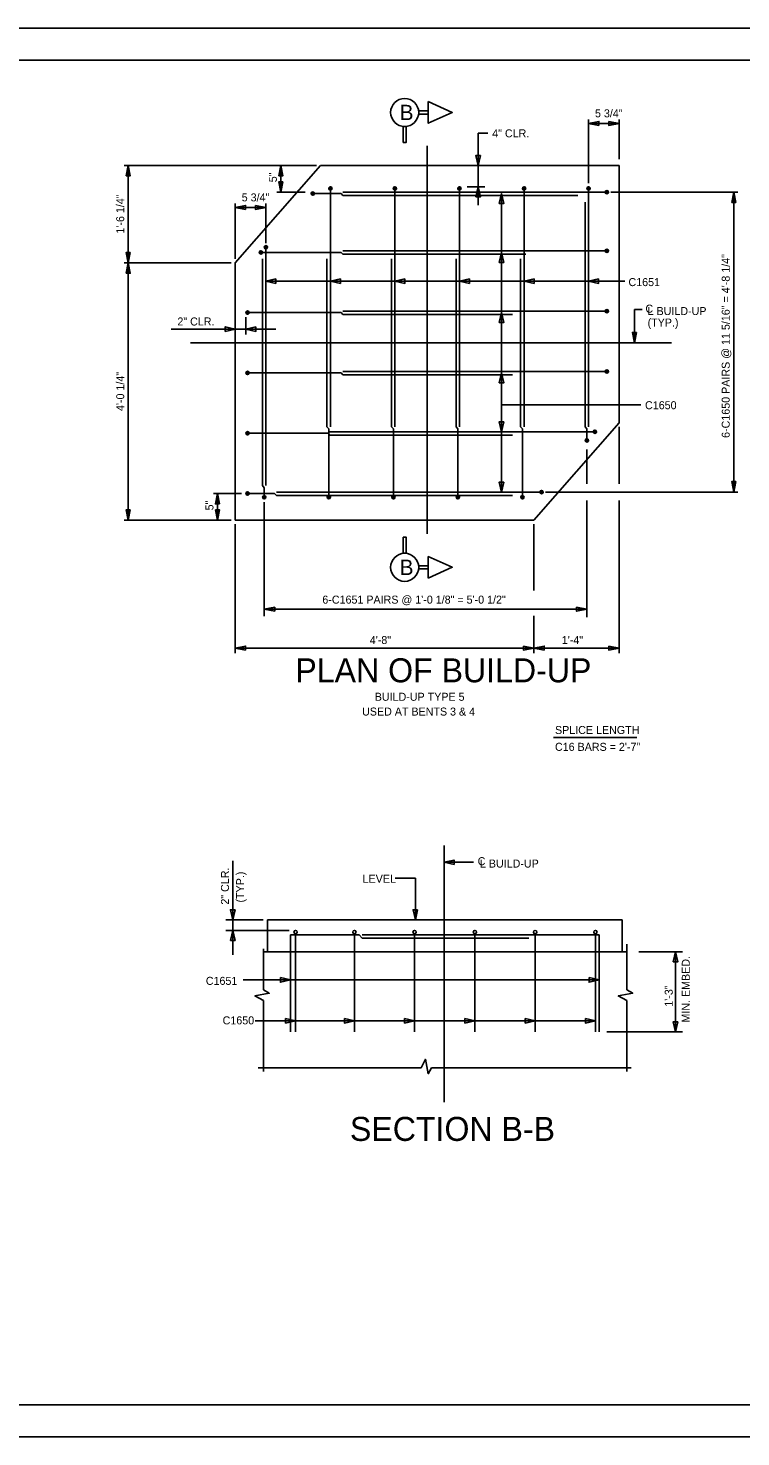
# Model space of a CAD drawing. Extents: x -133.1 to -97, y -110.1 to -88.1.
# Drawn here: x -121.69 to -110.56, y -110.1 to -88.1 of the extents above; entities that cross this region are included whole.
import ezdxf

# ---------------------------------------------------------------- set-up
doc = ezdxf.new("R2010")
doc.units = 0
for name, color, linetype in [('BR_AUTO DIMENSION', 7, 'Continuous'), ('BR_BORDER LINES', 7, 'Continuous'), ('BR_CENTER LINES', 7, 'Continuous'), ('BR_CONCRETE', 7, 'Continuous'), ('BR_REBAR', 7, 'Continuous'), ('BR_TEXT', 7, 'Continuous'), ('Default', 7, 'Continuous'), ('Level 31', 7, 'Continuous')]:
    doc.layers.add(name, color=color, linetype=linetype)

msp = doc.modelspace()

# ---------------------------------------------------------------- linework, layer by layer
at = {"layer": 'BR_AUTO DIMENSION'}
for p, q in [((-112.936, -90.525), (-112.936, -89.528)), ((-112.457, -90.148), (-112.457, -89.528)), ((-114.66, -90.866), (-114.66, -89.745)), ((-114.507, -89.745), (-114.66, -89.745)), ((-112.936, -89.59), (-112.457, -89.59)), ((-117.186, -90.245), (-120.191, -90.245)), ((-120.128, -91.766), (-120.128, -90.245)), ((-117.744, -90.245), (-117.744, -90.662)), ((-114.835, -90.579), (-114.554, -90.579)), ((-118.457, -91.704), (-118.457, -90.841)), ((-117.978, -91.461), (-117.978, -90.841)), ((-117.365, -90.662), (-117.806, -90.662)), ((-114.296, -90.685), (-114.296, -95.347)), ((-112.587, -90.662), (-110.605, -90.662)), ((-110.668, -95.347), (-110.668, -90.662)), ((-118.457, -90.903), (-117.978, -90.903)), ((-118.519, -91.766), (-120.191, -91.766)), ((-118.519, -91.766), (-120.191, -91.766)), ((-120.128, -95.787), (-120.128, -91.766)), ((-117.978, -92.053), (-112.371, -92.053)), ((-118.29, -92.617), (-118.29, -92.887)), ((-112.096, -92.498), (-112.219, -92.498)), ((-112.219, -92.498), (-112.219, -93.016)), ((-117.822, -92.803), (-119.456, -92.803)), ((-114.296, -93.983), (-112.117, -93.983)), ((-112.457, -94.329), (-112.457, -95.217)), ((-112.961, -94.682), (-112.961, -95.217)), ((-118.356, -95.37), (-118.797, -95.37)), ((-118.734, -95.787), (-118.734, -95.37)), ((-113.606, -95.347), (-110.605, -95.347)), ((-112.961, -95.477), (-112.961, -97.301)), ((-112.457, -95.477), (-112.457, -97.866)), ((-118.002, -95.504), (-118.002, -97.285)), ((-118.519, -95.787), (-120.191, -95.787)), ((-118.457, -95.85), (-118.457, -97.866)), ((-113.79, -95.85), (-113.79, -96.883)), ((-118.002, -97.178), (-112.961, -97.178)), ((-113.79, -97.279), (-113.79, -97.866)), ((-118.457, -97.784), (-113.79, -97.784)), ((-113.79, -97.784), (-112.457, -97.784)), ((-113.486, -99.183), (-112.181, -99.183)), ((-118.495, -101.109), (-118.495, -102.574)), ((-115.194, -101.13), (-114.735, -101.13)), ((-115.959, -101.376), (-115.642, -101.376)), ((-115.642, -101.376), (-115.642, -102.026)), ((-118.022, -102.026), (-118.604, -102.026)), ((-117.616, -102.193), (-118.604, -102.193)), ((-112.149, -102.527), (-111.47, -102.527)), ((-111.576, -102.527), (-111.576, -103.777)), ((-112.771, -102.966), (-118.331, -102.966)), ((-112.828, -103.606), (-118.147, -103.606)), ((-116.595, -103.606), (-116.675, -103.606)), ((-116.348, -103.606), (-116.428, -103.606)), ((-115.653, -103.606), (-115.733, -103.606)), ((-114.712, -103.606), (-114.792, -103.606)), ((-113.77, -103.606), (-113.85, -103.606)), ((-112.828, -103.606), (-112.908, -103.606)), ((-112.65, -103.777), (-111.47, -103.777))]:
    msp.add_line(p, q, dxfattribs=at)
for points in [[(-112.774, -89.621), (-112.936, -89.59), (-112.774, -89.559)], [(-112.619, -89.559), (-112.457, -89.59), (-112.619, -89.621)], [(-114.624, -90.089), (-114.66, -90.245), (-114.696, -90.089)], [(-120.16, -90.408), (-120.128, -90.245), (-120.097, -90.408)], [(-117.775, -90.408), (-117.744, -90.245), (-117.712, -90.408)], [(-117.712, -90.5), (-117.744, -90.662), (-117.775, -90.5)], [(-114.696, -90.735), (-114.66, -90.579), (-114.624, -90.735)], [(-114.332, -90.841), (-114.296, -90.685), (-114.26, -90.841)], [(-110.699, -90.825), (-110.668, -90.662), (-110.637, -90.825)], [(-118.294, -90.934), (-118.457, -90.903), (-118.294, -90.872)], [(-118.14, -90.872), (-117.978, -90.903), (-118.14, -90.934)], [(-120.097, -91.604), (-120.128, -91.766), (-120.16, -91.604)], [(-114.332, -91.76), (-114.296, -91.604), (-114.26, -91.76)], [(-120.16, -91.929), (-120.128, -91.766), (-120.097, -91.929)], [(-117.822, -92.017), (-117.978, -92.053), (-117.822, -92.089)], [(-116.813, -92.017), (-116.969, -92.053), (-116.813, -92.089)], [(-115.805, -92.017), (-115.961, -92.053), (-115.805, -92.089)], [(-114.797, -92.017), (-114.953, -92.053), (-114.797, -92.089)], [(-113.788, -92.017), (-113.944, -92.053), (-113.788, -92.089)], [(-112.78, -92.017), (-112.936, -92.053), (-112.78, -92.089)], [(-114.332, -92.701), (-114.296, -92.545), (-114.26, -92.701)], [(-118.613, -92.839), (-118.457, -92.803), (-118.613, -92.767)], [(-118.134, -92.767), (-118.29, -92.803), (-118.134, -92.839)], [(-112.188, -92.854), (-112.219, -93.016), (-112.251, -92.854)], [(-114.332, -93.643), (-114.296, -93.487), (-114.26, -93.643)], [(-114.26, -94.25), (-114.296, -94.406), (-114.332, -94.25)], [(-114.26, -95.191), (-114.296, -95.347), (-114.332, -95.191)], [(-110.637, -95.185), (-110.668, -95.347), (-110.699, -95.185)], [(-118.703, -95.533), (-118.734, -95.37), (-118.765, -95.533)], [(-120.097, -95.625), (-120.128, -95.787), (-120.16, -95.625)], [(-118.765, -95.625), (-118.734, -95.787), (-118.703, -95.625)], [(-117.84, -97.209), (-118.002, -97.178), (-117.84, -97.147)], [(-113.123, -97.147), (-112.961, -97.178), (-113.123, -97.209)], [(-118.294, -97.815), (-118.457, -97.784), (-118.294, -97.752)], [(-113.953, -97.752), (-113.79, -97.784), (-113.953, -97.815)], [(-113.628, -97.815), (-113.79, -97.784), (-113.628, -97.752)], [(-112.619, -97.752), (-112.457, -97.784), (-112.619, -97.815)], [(-115.038, -101.166), (-115.194, -101.13), (-115.038, -101.094)], [(-118.459, -101.87), (-118.495, -102.026), (-118.531, -101.87)], [(-115.606, -101.87), (-115.642, -102.026), (-115.678, -101.87)], [(-118.531, -102.349), (-118.495, -102.193), (-118.459, -102.349)], [(-111.612, -102.683), (-111.576, -102.527), (-111.54, -102.683)], [(-117.75, -102.93), (-117.594, -102.966), (-117.75, -103.002)], [(-112.927, -102.93), (-112.771, -102.966), (-112.927, -103.002)], [(-117.669, -103.57), (-117.513, -103.606), (-117.669, -103.642)], [(-116.751, -103.57), (-116.595, -103.606), (-116.751, -103.642)], [(-115.809, -103.57), (-115.653, -103.606), (-115.809, -103.642)], [(-114.868, -103.57), (-114.712, -103.606), (-114.868, -103.642)], [(-113.926, -103.57), (-113.77, -103.606), (-113.926, -103.642)], [(-112.984, -103.57), (-112.828, -103.606), (-112.984, -103.642)], [(-111.54, -103.621), (-111.576, -103.777), (-111.612, -103.621)]]:
    msp.add_lwpolyline(points, close=True, dxfattribs=at)
at = {"layer": 'BR_BORDER LINES'}
for p, q in [((-97.642, -88.603), (-131.308, -88.603)), ((-131.308, -109.603), (-97.642, -109.603))]:
    msp.add_line(p, q, dxfattribs=at)
at = {"layer": 'BR_CENTER LINES'}
for p, q in [((-115.457, -89.942), (-115.457, -95.998)), ((-119.154, -93.016), (-111.642, -93.016)), ((-115.194, -100.868), (-115.194, -104.877))]:
    msp.add_line(p, q, dxfattribs=at)
at = {"layer": 'BR_CONCRETE'}
for p, q in [((-118.457, -91.766), (-117.124, -90.245)), ((-112.457, -90.245), (-117.124, -90.245)), ((-112.457, -94.266), (-112.457, -90.245)), ((-118.457, -91.766), (-118.457, -95.787)), ((-113.79, -95.787), (-112.457, -94.266)), ((-113.79, -95.787), (-118.457, -95.787)), ((-117.953, -102.026), (-117.953, -102.527)), ((-117.953, -102.026), (-112.412, -102.026)), ((-112.412, -102.026), (-112.412, -102.527)), ((-118.015, -102.527), (-112.338, -102.527))]:
    msp.add_line(p, q, dxfattribs=at)
at = {"layer": 'BR_REBAR'}
for p, q in [((-116.969, -90.579), (-116.969, -94.329)), ((-115.961, -90.579), (-115.961, -94.329)), ((-114.953, -90.579), (-114.953, -94.329)), ((-113.944, -90.579), (-113.944, -94.329)), ((-112.936, -90.579), (-112.936, -94.329)), ((-117.271, -90.685), (-116.802, -90.685)), ((-116.802, -90.685), (-116.774, -90.716)), ((-116.774, -90.662), (-112.624, -90.662)), ((-116.774, -90.716), (-113.104, -90.716)), ((-112.99, -90.818), (-112.99, -94.329)), ((-117.978, -91.497), (-117.978, -95.247)), ((-118.081, -91.604), (-116.802, -91.604)), ((-118.032, -91.704), (-118.032, -95.247)), ((-117.023, -91.704), (-117.023, -94.329)), ((-116.802, -91.604), (-116.774, -91.634)), ((-116.774, -91.581), (-112.624, -91.581)), ((-116.774, -91.634), (-113.914, -91.634)), ((-116.015, -91.704), (-116.015, -94.329)), ((-115.005, -91.704), (-115.005, -94.329)), ((-113.998, -91.704), (-113.998, -94.329)), ((-118.29, -92.545), (-116.802, -92.545)), ((-116.802, -92.545), (-116.774, -92.576)), ((-116.774, -92.522), (-112.624, -92.522)), ((-116.774, -92.576), (-114.124, -92.576)), ((-118.29, -93.487), (-116.802, -93.487)), ((-116.802, -93.487), (-116.774, -93.517)), ((-116.774, -93.464), (-112.624, -93.464)), ((-116.774, -93.517), (-114.124, -93.517)), ((-117.023, -94.329), (-116.994, -94.36)), ((-116.994, -94.36), (-116.994, -95.454)), ((-116.015, -94.329), (-115.986, -94.36)), ((-115.986, -94.36), (-115.986, -95.454)), ((-115.005, -94.329), (-114.977, -94.359)), ((-114.977, -94.359), (-114.977, -95.454)), ((-113.998, -94.329), (-113.969, -94.36)), ((-113.969, -94.36), (-113.969, -95.454)), ((-112.99, -94.329), (-112.961, -94.36)), ((-112.961, -94.36), (-112.961, -94.568)), ((-118.29, -94.429), (-117.006, -94.429)), ((-117.006, -94.429), (-116.978, -94.459)), ((-116.978, -94.406), (-112.811, -94.406)), ((-116.978, -94.459), (-114.124, -94.459)), ((-118.032, -95.247), (-118.002, -95.279)), ((-118.29, -95.37), (-117.842, -95.37)), ((-118.002, -95.279), (-118.002, -95.454)), ((-117.842, -95.37), (-117.813, -95.401)), ((-117.813, -95.401), (-114.124, -95.401)), ((-117.809, -95.347), (-113.643, -95.347)), ((-117.594, -102.265), (-117.594, -103.777)), ((-116.521, -102.265), (-117.594, -102.265)), ((-117.513, -103.777), (-117.513, -102.245)), ((-116.595, -103.777), (-116.595, -102.245)), ((-116.521, -102.265), (-116.473, -102.317)), ((-112.771, -102.264), (-116.473, -102.264)), ((-115.653, -103.777), (-115.653, -102.245)), ((-114.712, -103.777), (-114.712, -102.245)), ((-113.77, -103.777), (-113.77, -102.245)), ((-112.828, -103.777), (-112.828, -102.245)), ((-112.771, -102.264), (-112.771, -103.777)), ((-113.87, -102.317), (-116.473, -102.317))]:
    msp.add_line(p, q, dxfattribs=at)
for centre, radius in [((-116.969, -90.605), 0.026), ((-115.961, -90.605), 0.026), ((-114.953, -90.605), 0.026), ((-113.944, -90.605), 0.026), ((-112.936, -90.605), 0.026), ((-112.65, -90.662), 0.026), ((-117.245, -90.685), 0.026), ((-117.978, -91.523), 0.026), ((-118.055, -91.604), 0.026), ((-112.65, -91.581), 0.026), ((-118.264, -92.545), 0.026), ((-112.65, -92.522), 0.026), ((-118.264, -93.487), 0.026), ((-112.65, -93.464), 0.026), ((-112.837, -94.406), 0.026), ((-118.264, -94.429), 0.026), ((-112.961, -94.542), 0.026), ((-118.264, -95.37), 0.026), ((-118.002, -95.428), 0.026), ((-116.994, -95.428), 0.026), ((-115.986, -95.428), 0.026), ((-114.977, -95.428), 0.026), ((-113.969, -95.428), 0.026), ((-113.669, -95.347), 0.026), ((-117.513, -102.219), 0.0261), ((-116.595, -102.219), 0.0261), ((-115.653, -102.219), 0.0261), ((-114.712, -102.219), 0.0261), ((-113.77, -102.219), 0.0261), ((-112.828, -102.219), 0.0261)]:
    msp.add_circle(centre, radius, dxfattribs=at)
at = {"layer": 'BR_TEXT'}
for points in [[(-115.44, -89.25), (-115.065, -89.419), (-115.44, -89.588)], [(-115.59, -89.444), (-115.44, -89.444), (-115.44, -89.394), (-115.59, -89.394)], [(-115.834, -89.888), (-115.784, -89.888), (-115.784, -89.638), (-115.834, -89.638)], [(-115.834, -96.054), (-115.784, -96.054), (-115.784, -96.304), (-115.834, -96.304)], [(-115.44, -96.692), (-115.065, -96.523), (-115.44, -96.354)], [(-115.59, -96.498), (-115.44, -96.498), (-115.44, -96.548), (-115.59, -96.548)]]:
    msp.add_lwpolyline(points, close=True, dxfattribs=at)
for centre in [(-115.809, -89.419), (-115.809, -96.523)]:
    msp.add_circle(centre, 0.219, dxfattribs=at)
at = {"layer": 'Default'}
for p, q in [((-118.015, -103.124), (-118.015, -102.481)), ((-112.338, -103.124), (-112.338, -102.407)), ((-118.015, -104.398), (-118.015, -103.286)), ((-112.338, -104.398), (-112.338, -103.286)), ((-118.096, -104.339), (-115.552, -104.339)), ((-115.391, -104.339), (-112.272, -104.339))]:
    msp.add_line(p, q, dxfattribs=at)
for points in [[(-118.015, -103.124), (-117.924, -103.174), (-118.15, -103.217), (-118.015, -103.286)], [(-112.338, -103.124), (-112.246, -103.174), (-112.473, -103.217), (-112.338, -103.286)], [(-115.391, -104.339), (-115.44, -104.431), (-115.483, -104.205), (-115.552, -104.339)]]:
    msp.add_lwpolyline(points, dxfattribs=at)
at = {"layer": 'Level 31'}
msp.add_lwpolyline([(-133.141, -110.103), (-97.141, -110.103), (-97.141, -88.103), (-133.141, -88.103)], close=True, dxfattribs=at)

# ---------------------------------------------------------------- texts
at = {"layer": 'BR_AUTO DIMENSION'}
for s, p in [('5 3/4"', (-112.835, -89.495)), ('4" CLR.', (-114.441, -89.808)), ('5 3/4"', (-118.355, -90.808)), ('C1651', (-112.312, -92.131)), ('2" CLR.', (-119.36, -92.746)), ('C', (-112.047, -92.546)), ('L BUILD-UP', (-112.013, -92.583)), ('(TYP.)', (-112.013, -92.763)), ('C1650', (-112.053, -94.054)), ('6-C1651 PAIRS @ 1\'-0 1/8" = 5\'-0 1/2"', (-117.095, -97.09)), ('4\'-8"', (-116.354, -97.721)), ('1\'-4"', (-113.354, -97.721)), ('BUILD-UP TYPE 5', (-116.276, -98.607)), ('USED AT BENTS 3 & 4', (-116.474, -98.838)), ('SPLICE LENGTH', (-113.46, -99.126)), ('C16 BARS = 2\'-7"', (-113.46, -99.389)), ('C', (-114.668, -101.175)), ('L BUILD-UP', (-114.633, -101.212))]:
    msp.add_text(s, height=0.125, dxfattribs=at).set_placement(p)
for s, rotation, p in [('5"', 90, (-117.806, -90.509)), ('1\'-6 1/4"', 90, (-120.191, -91.311)), ('6-C1650 PAIRS @ 11 5/16" = 4\'-8 1/4"', 90, (-110.73, -94.502)), ('4\'-0 1/4"', 90, (-120.191, -94.082)), ('5"', 90, (-118.797, -95.634)), ('2" CLR.', 90, (-118.554, -101.791)), ('(TYP.)', 90, (-118.317, -101.758)), ('LEVEL', 360, (-116.466, -101.449)), ('MIN. EMBED.', 90, (-111.354, -103.633)), ('C1651', 360, (-118.916, -103.044)), ('1\'-3" ', 90, (-111.62, -103.385)), ('C1650', 360, (-118.653, -103.661))]:
    msp.add_text(s, height=0.125, rotation=rotation, dxfattribs=at).set_placement(p)
at = {"layer": 'BR_TEXT'}
for s, height, p in [('B', 0.24, (-115.885, -89.539)), ('B', 0.24, (-115.885, -96.643)), ('PLAN OF BUILD-UP', 0.375, (-117.517, -98.319))]:
    msp.add_text(s, height=height, dxfattribs=at).set_placement(p)
msp.add_text('SECTION B-B', height=0.375, rotation=360, dxfattribs=at).set_placement((-116.664, -105.481))

doc.saveas('drawing.dxf')
